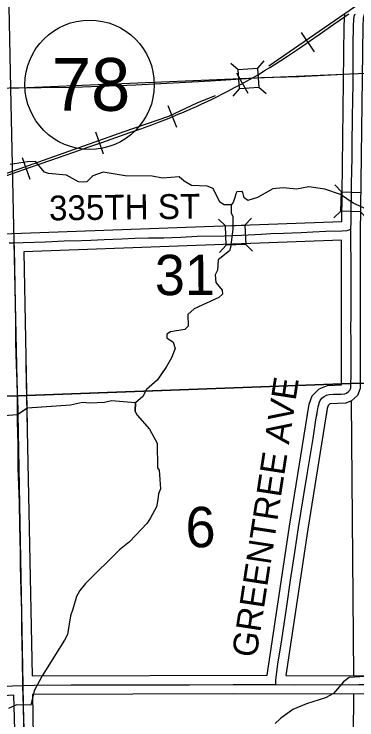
# Model space of a CAD drawing. Extents: x 10133 to 81668, y 7924 to 11018.
# Drawn here: x 11285.8 to 11451.5, y 8876.1 to 9217.2 of the extents above; entities that cross this region are included whole.
import ezdxf

# ---------------------------------------------------------------- set-up
doc = ezdxf.new("R2010")
doc.units = 0
for name, color, linetype in [('tdCoCityStreetMajor', 7, 'Continuous'), ('tdCoCityStreetMinor', 7, 'Continuous'), ('tdCoHydroRiver', 7, 'Continuous'), ('tdCoPriNonDiv', 7, 'Continuous'), ('tdCoRRCL', 7, 'Continuous'), ('tdCoRROwnerTxt', 7, 'Continuous'), ('tdCoShieldCoRte', 7, 'Continuous'), ('tdCoShieldCoRteHrd', 7, 'Continuous'), ('tdCoShieldStRte', 7, 'Continuous'), ('tdCoStrucNonDivPri', 7, 'Continuous'), ('tdCoStrucSec', 7, 'Continuous'), ('tdCoSurfConc', 7, 'Continuous'), ('tdCoTwpNameTxt', 7, 'Continuous'), ('tdCoTwpRngTxt', 7, 'Continuous')]:
    doc.layers.add(name, color=color, linetype=linetype)

msp = doc.modelspace()

# ---------------------------------------------------------------- linework, layer by layer
at = {"layer": 'tdCoCityStreetMajor'}
for points in [[(11449.75, 9188.33), (11449.72, 9189.86), (11449.7, 9191.56), (11449.77, 9195.26), (11449.82, 9202.37), (11449.96, 9211.58), (11450.08, 9214.49), (11450.18, 9216.24), (11450.65, 9217.4)], [(11287.58, 9017.69), (11287.51, 9020.26), (11287.46, 9028.4), (11287.46, 9032.34), (11287.46, 9032.68), (11287.46, 9035.79), (11286.87, 9052.61), (11286.62, 9059.22), (11286.67, 9068.2), (11286.33, 9086.15), (11285.96, 9104.2), (11285.91, 9106.73)], [(11290.13, 8892.79), (11290.1, 8894.02), (11289.95, 8904.79), (11289.77, 8914.07), (11289.51, 8919.25), (11289.55, 8928.72), (11289.32, 8938.67), (11288.95, 8950.62), (11288.92, 8957.13), (11288.66, 8969.89), (11288.4, 8981.03), (11287.85, 8997.82), (11287.81, 9009.55), (11287.51, 9020.26), (11287.46, 9028.4), (11287.46, 9032.34), (11287.46, 9032.68), (11287.46, 9035.8), (11287.04, 9047.67)]]:
    msp.add_lwpolyline(points, dxfattribs=at)
at = {"layer": 'tdCoCityStreetMinor'}
for points in [[(11448.68, 9113.25), (11448.72, 9116.64), (11448.8, 9123.3), (11448.95, 9130.18), (11448.97, 9135.36), (11449.04, 9141.35), (11449.22, 9147.91), (11449.22, 9152.82), (11449.32, 9158.56), (11449.39, 9162.93), (11449.44, 9169.41), (11449.6, 9173.71), (11449.79, 9185.4), (11449.75, 9188.33)], [(11283.47, 9106.67), (11285.91, 9106.73), (11290.27, 9106.84), (11301.03, 9107.21), (11310.03, 9107.58), (11318.39, 9107.83), (11322.85, 9107.98), (11329.38, 9108.22), (11337.84, 9108.54), (11344.18, 9108.86), (11350.84, 9109.04), (11358.24, 9109.13), (11362.06, 9109.23), (11366.43, 9109.48), (11374.32, 9109.83), (11387.36, 9110.12), (11395.77, 9110.42), (11405.39, 9110.81), (11409.93, 9111.11), (11416.12, 9111.4), (11420.21, 9111.58), (11424.55, 9111.7), (11430.17, 9111.97), (11436.58, 9112.24), (11444.45, 9112.51), (11446.82, 9112.66), (11448.68, 9113.25)], [(11432.14, 9023.12), (11432.4, 9024.53), (11432.82, 9027.47), (11433.41, 9029.69), (11433.78, 9030.43), (11434.67, 9031.66), (11435.65, 9032.37), (11436.86, 9033.04), (11438.1, 9033.34), (11440.22, 9033.48), (11443.92, 9033.46), (11445.72, 9033.66), (11446.58, 9034.1), (11447.52, 9034.79), (11448.11, 9035.51), (11448.43, 9036.07), (11448.6, 9036.62), (11448.63, 9036.99), (11448.64, 9037.81), (11448.65, 9038.75), (11448.7, 9042.02), (11448.72, 9047.94), (11448.72, 9053.66), (11448.75, 9059.18), (11448.65, 9065.64), (11448.72, 9071.41), (11448.75, 9077.73), (11448.72, 9082.41), (11448.72, 9087.74), (11448.7, 9093.83), (11448.7, 9099.21), (11448.65, 9105.17), (11448.65, 9111.14), (11448.68, 9113.25)], [(11412.41, 8893.16), (11412.38, 8894.08), (11412.38, 8895.41), (11413.38, 8903.11), (11415.23, 8914.84), (11417.67, 8931.15), (11419.52, 8943.69), (11421.74, 8958.08), (11423.37, 8969.06), (11425.81, 8983.93), (11427.55, 8994.66), (11430.36, 9012.05), (11431.77, 9021.11), (11432.4, 9024.53), (11432.82, 9027.47), (11433.41, 9029.69), (11433.78, 9030.43), (11434.67, 9031.66), (11435.65, 9032.38), (11436.86, 9033.04), (11438.1, 9033.34), (11440.22, 9033.49), (11443.92, 9033.46), (11445.72, 9033.66), (11446.58, 9034.1), (11447.52, 9034.79), (11448.11, 9035.51), (11448.43, 9036.08), (11448.6, 9036.62), (11448.63, 9036.99), (11448.64, 9037.81), (11448.65, 9038.75), (11448.7, 9042.02), (11448.72, 9047.94), (11448.72, 9053.66), (11448.72, 9053.75)], [(11132.26, 8883.01), (11137.84, 8883.11), (11139.75, 8883.2), (11143.14, 8883.42), (11146.24, 8883.74), (11153.6, 8884.22), (11167.14, 8885.07), (11182.16, 8886.03), (11197.07, 8886.99), (11212.09, 8887.95), (11231.54, 8889.28), (11246.52, 8890.21), (11266.72, 8891.54), (11284.99, 8892.61), (11290.13, 8892.79)], [(11290.13, 8892.79), (11295.54, 8892.98), (11313.48, 8893.09), (11329.9, 8893.06), (11346.73, 8893.02), (11370.7, 8893.13), (11391.68, 8893.21), (11408.17, 8893.17), (11412.41, 8893.16)], [(11293.46, 8703.76), (11293.21, 8716.99), (11292.65, 8738.22), (11292.62, 8741.42), (11292.51, 8750.76), (11292.25, 8765.48), (11292.06, 8783.38), (11291.84, 8794.07), (11291.69, 8809.94), (11291.51, 8821.74), (11291.21, 8839.17), (11291.06, 8848.97), (11290.8, 8865.95), (11290.47, 8877.16), (11290.13, 8892.79)], [(11412.41, 8893.16), (11421.42, 8893.13), (11452.49, 8893.17), (11490, 8893.17), (11515.67, 8893.17), (11530.73, 8893.06), (11548, 8892.98), (11571.01, 8893.06), (11587.84, 8892.98), (11602.45, 8892.95)]]:
    msp.add_lwpolyline(points, dxfattribs=at)
at = {"layer": 'tdCoHydroRiver'}
for points in [[(11390.74, 9125.03), (11387.43, 9124.98), (11385.27, 9126.36), (11382.09, 9132.94), (11379.22, 9134.08), (11371.64, 9134.42), (11368.06, 9136.49), (11365.65, 9138.58), (11357.61, 9137.98), (11352.62, 9138.84), (11339.6, 9139.09), (11328.91, 9140.81), (11323.97, 9139.07), (11320.94, 9136.18), (11319.52, 9135.92), (11316.91, 9136.11), (11311.18, 9139.33), (11302.4, 9140.13), (11300.5, 9140.81), (11296.15, 9145.94), (11292.36, 9145.88), (11283.86, 9144.55)], [(11457.56, 9122.37), (11449.69, 9125.79), (11443.7, 9129.95), (11436.08, 9132.66), (11428.25, 9133.72), (11422.35, 9132.67), (11415.94, 9133.27), (11410.98, 9132.71), (11403.47, 9128.56), (11398.76, 9127.06), (11397.08, 9128.46), (11396.33, 9131.05), (11396.08, 9131.52), (11393.48, 9131.24), (11393.02, 9130.28), (11392.58, 9128.62), (11391.67, 9126.23), (11390.74, 9125.03)], [(11390.74, 9125.03), (11390.81, 9121.01), (11391.54, 9119.6), (11391.65, 9113.21), (11390.38, 9104.43), (11389.93, 9102.76), (11384.56, 9098.41), (11384.17, 9093.43), (11383.02, 9091.28), (11383.32, 9087.5), (11386.46, 9083.76), (11386.5, 9081.87), (11384.87, 9080.18), (11372.88, 9074.77), (11369.85, 9072.11), (11369.94, 9066.43), (11368.31, 9064.75), (11361.46, 9063.69), (11359.59, 9062.47), (11359.62, 9060.81), (11362.73, 9058.73), (11363.73, 9055.67), (11361.91, 9051.14), (11359.38, 9046.6), (11354.99, 9040.37), (11349.86, 9035.79), (11348.02, 9032.44), (11344.52, 9029.3)], [(11359.23, 9046.39), (11354.98, 9040.37), (11349.85, 9035.79), (11348.01, 9032.44), (11344.51, 9029.3)], [(11344.52, 9029.3), (11332.9, 9030.29), (11329.6, 9029.53), (11322.5, 9029.17), (11318.94, 9029.58), (11313.04, 9028.3), (11292.23, 9026.77), (11287.55, 9023.61), (11280.93, 9023.02), (11279.04, 9022.28), (11274.13, 9018.65), (11274.05, 9018.47)], [(11344.51, 9029.3), (11332.89, 9030.29), (11329.59, 9029.53), (11322.49, 9029.17), (11318.93, 9029.58), (11313.04, 9028.3), (11292.22, 9026.77), (11287.54, 9023.61), (11280.92, 9023.02)], [(11344.51, 9029.3), (11344.34, 9025.27), (11345.32, 9023.4), (11351.36, 9016.63), (11355.02, 9009.82), (11355.22, 8997.99), (11355.95, 8996.82), (11356.58, 8987.83), (11355.67, 8985.45), (11355.24, 8982.6), (11354.59, 8979.03), (11351.84, 8973.78), (11350.23, 8971.15), (11341.61, 8962.24), (11336.71, 8958.37), (11320.4, 8941.99), (11317.62, 8938.63), (11316.01, 8935.76), (11314.22, 8929.58), (11313.09, 8926.48), (11311.58, 8917.45), (11310.21, 8914.59), (11299.37, 8897.36), (11295.46, 8890.19), (11293.92, 8883.3), (11287.05, 8883.42), (11283.06, 8881.69)], [(11348.38, 9019.98), (11345.33, 9023.4), (11344.35, 9025.27), (11344.52, 9029.3)], [(11460.86, 8897.47), (11447.85, 8896.54), (11445.04, 8894.6), (11440.17, 8888.83), (11436.41, 8886.87), (11427.23, 8883.88), (11420.64, 8881.16), (11414.56, 8876.8), (11412, 8874.39)]]:
    msp.add_lwpolyline(points, dxfattribs=at)
at = {"layer": 'tdCoPriNonDiv'}
for points in [[(11456.75, 9222.11), (11454.63, 9215.25), (11454.45, 9211.45), (11453.15, 9111.11), (11453.09, 9036.32), (11451.81, 9032.96), (11448.95, 9030.28), (11446.21, 9029.19), (11438.5, 9028.81), (11437.64, 9028.09), (11437.23, 9026.57), (11436.7, 9023.29)], [(11143.3, 9108.7), (11170.54, 9114.42), (11174.02, 9113.87), (11177.47, 9110.84), (11182.09, 9109.82), (11206.22, 9110.01), (11206.03, 9114.93), (11204.9, 9119.98), (11213.68, 9121.96), (11214.95, 9116.26), (11215.23, 9110.16), (11271.49, 9110.67), (11444.23, 9117.01), (11445.46, 9211.77), (11445.79, 9217.23)], [(11427.55, 9022.95), (11428.47, 9028.63), (11429.93, 9032.75), (11433.24, 9036.17), (11437.41, 9037.78), (11444.14, 9038.01), (11444.15, 9108), (11290.49, 9102.35), (11292.17, 9017.86)], [(11408.14, 8897.67), (11418.92, 8969.72), (11428.47, 9028.63), (11429.93, 9032.76), (11433.24, 9036.17), (11437.41, 9037.78), (11444.14, 9038.01), (11444.14, 9053.58)], [(11453.1, 9053.84), (11453.09, 9036.32), (11451.81, 9032.96), (11448.95, 9030.28), (11446.21, 9029.19), (11438.5, 9028.81), (11437.64, 9028.09), (11437.23, 9026.57), (11427.82, 8968.37), (11417.21, 8897.64), (11597.95, 8897.46)], [(11291.57, 9047.85), (11294.55, 8897.45), (11408.14, 8897.67)], [(11286.31, 8865.85), (11285.73, 8888.14), (11144.9, 8879.08), (11144.31, 8878.21), (11146.22, 8766.24)], [(11595.38, 8746.02), (11596.14, 8813.76), (11597.55, 8822.33), (11597.96, 8884), (11597.96, 8888.46), (11391.68, 8888.71), (11294.72, 8888.45), (11297.06, 8746), (11483.67, 8746.8), (11524.54, 8746.1), (11595.38, 8746.02)]]:
    msp.add_lwpolyline(points, dxfattribs=at)
at = {"layer": 'tdCoRRCL'}
for p, q in [((11431.11, 9199.01), (11424.76, 9208.3)), ((11398.96, 9178.79), (11393.47, 9188.61)), ((11364.5, 9162.4), (11360.24, 9172.81)), ((11328.97, 9149.51), (11325.27, 9160.14)), ((11293.57, 9137.2), (11289.83, 9147.81))]:
    msp.add_line(p, q, dxfattribs=at)
for points in [[(11408.96, 9192.14), (11496.88, 9252.86), (11521.5, 9269.09), (11537.38, 9279.92), (11549.05, 9286.44), (11568.06, 9294.84)], [(11278.95, 9138.04), (11287.78, 9141.12), (11293.35, 9143.09), (11298.91, 9145.06), (11307.34, 9147.96), (11314.76, 9150.52), (11321.48, 9152.86), (11328.2, 9155.2), (11334.97, 9157.56), (11341.73, 9159.92), (11347.04, 9161.83), (11352.35, 9163.73), (11354.88, 9164.66), (11357.42, 9165.58), (11360.01, 9166.64), (11362.61, 9167.7), (11365.2, 9168.79), (11367.8, 9169.87), (11370.89, 9171.22), (11373.97, 9172.58), (11376.61, 9173.78), (11379.24, 9174.98), (11381.66, 9176.16), (11384.08, 9177.34), (11386.64, 9178.67), (11389.19, 9180.01), (11392.36, 9181.66), (11395.52, 9183.31), (11399.63, 9185.61), (11403.74, 9187.92), (11405.51, 9189), (11407.28, 9190.08), (11409.38, 9191.41), (11411.49, 9192.75), (11414.75, 9194.82), (11418.01, 9196.88), (11423.29, 9200.49), (11428.58, 9204.1), (11433.27, 9207.3), (11440.47, 9212.33), (11447.66, 9217.37)], [(11383.11, 9177.72), (11374.43, 9174.35), (11360.55, 9167.76), (11338.88, 9160.33), (11251.25, 9129.22), (11226.5, 9121.28), (11195.58, 9114.67), (11163.03, 9105.91), (11145.32, 9102.57), (11125.98, 9097.32), (11109.94, 9093.06), (11085.46, 9083.46), (11066.85, 9076.56), (10954.88, 9032.59)]]:
    msp.add_lwpolyline(points, dxfattribs=at)
at = {"layer": 'tdCoShieldCoRte'}
for points in [[(11440.93, 9134.74), (11444.14, 9131.32), (11453.52, 9131.03)], [(11440.44, 9118.72), (11443.85, 9121.94), (11444.14, 9131.32)], [(11456.45, 9118.23), (11453.23, 9121.65), (11443.85, 9121.94)], [(11384.64, 9118.04), (11388.07, 9114.84), (11397.45, 9115.17)], [(11400.65, 9118.6), (11397.45, 9115.17), (11397.78, 9105.79)], [(11385.2, 9102.03), (11388.4, 9105.46), (11388.07, 9114.84)], [(11401.14, 9102.66), (11397.78, 9105.79), (11388.4, 9105.46)]]:
    msp.add_lwpolyline(points, dxfattribs=at)
at = {"layer": 'tdCoShieldCoRteHrd'}
for points in [[(11291.99, 9032.85), (11444.14, 9038.58)], [(11291.99, 9032.85), (11444.15, 9038.58)]]:
    msp.add_lwpolyline(points, dxfattribs=at)
at = {"layer": 'tdCoStrucNonDivPri'}
for points in [[(11284.23, 9181.46), (11445.26, 9188.14)], [(11291.99, 9032.85), (11444.14, 9038.58)], [(11291.99, 9032.85), (11444.15, 9038.58)], [(11448.73, 9030.17), (11449.96, 8897.65)], [(11448.74, 9030.17), (11448.8, 9023.75)], [(11449.96, 8888.64), (11448.74, 8746.76)]]:
    msp.add_lwpolyline(points, dxfattribs=at)
at = {"layer": 'tdCoStrucSec'}
msp.add_lwpolyline([(10954.88, 9175.44), (11041.44, 9177.24), (11055.35, 9177.93), (11080.24, 9178.84), (11116.14, 9179.9), (11130.94, 9179.97), (11160.16, 9180.44), (11189.9, 9180.57), (11314.49, 9181.85), (11344.65, 9183.03), (11380.85, 9184.91), (11405.4, 9186.53), (11423.46, 9187.1), (11448.12, 9188.29), (11485.13, 9189.73)], dxfattribs=at)
at = {"layer": 'tdCoSurfConc'}
msp.add_circle((11322.34, 9183.04), 31.27, dxfattribs=at)
at = {"layer": 'tdCoTwpNameTxt'}
for points in [[(12204.65, 9594.91), (12205.81, 9506.76), (12207.26, 9355.85), (12207.65, 9199.23), (12206.71, 9053.29), (12058.44, 9052.45), (12055.44, 9052.43), (11906.7, 9050.03), (11903.62, 9049.96), (11751.72, 9046.27), (11602.3, 9041.92), (11599.58, 9041.89), (11448.66, 9038.75), (11287.47, 9032.68), (11137.48, 9029.42), (10987.91, 9025.85), (10954.88, 9025.06)], [(11287.47, 9032.68), (11284.23, 9181.46), (11281.14, 9331.19), (11278.77, 9457.01), (11277.18, 9480.27), (11277.53, 9527.34), (11276.22, 9594.91)], [(10954.88, 9025.06), (10987.91, 9025.85), (11137.48, 9029.42), (11287.46, 9032.68), (11448.65, 9038.75), (11599.58, 9041.89), (11602.29, 9041.92), (11751.71, 9046.27), (11903.62, 9049.96), (11906.69, 9050.03), (12055.44, 9052.43), (12058.43, 9052.45), (12206.7, 9053.29), (12354.1, 9050.96), (12408.9, 9050.4)], [(11287.46, 9032.68), (11290.13, 8892.79), (11292.62, 8741.42), (11295.44, 8590.24), (11296.31, 8510.55)]]:
    msp.add_lwpolyline(points, dxfattribs=at)
at = {"layer": 'tdCoTwpRngTxt'}
for points in [[(11390.56, 9193.45), (11394.11, 9190.38), (11403.47, 9191.07)], [(11406.53, 9194.63), (11403.47, 9191.07), (11404.16, 9181.72)], [(11391.73, 9177.47), (11394.8, 9181.03), (11394.11, 9190.38)], [(11407.63, 9178.72), (11404.16, 9181.72), (11394.8, 9181.03)]]:
    msp.add_lwpolyline(points, dxfattribs=at)

# ---------------------------------------------------------------- texts
at = {"layer": 'tdCoRROwnerTxt'}
for s, rotation, p in [('31', 0.2274, (11353.93, 9081.36)), ('6', 1.1429, (11368.89, 8959.42))]:
    msp.add_text(s, height=19.5, rotation=rotation, dxfattribs=at).set_placement(p)
at = {"layer": 'tdCoShieldStRte'}
for s, rotation, p in [('335TH ST', 0.7076, (11302.77, 9117.47)), ('GREENTREE AVE', 81.3252, (11402.94, 8905.84))]:
    msp.add_text(s, height=12, rotation=rotation, dxfattribs=at).set_placement(p)
at = {"layer": 'tdCoSurfConc'}
msp.add_text('78', height=25.5, dxfattribs=at).set_placement((11304.07, 9170.46))

doc.saveas('drawing.dxf')
